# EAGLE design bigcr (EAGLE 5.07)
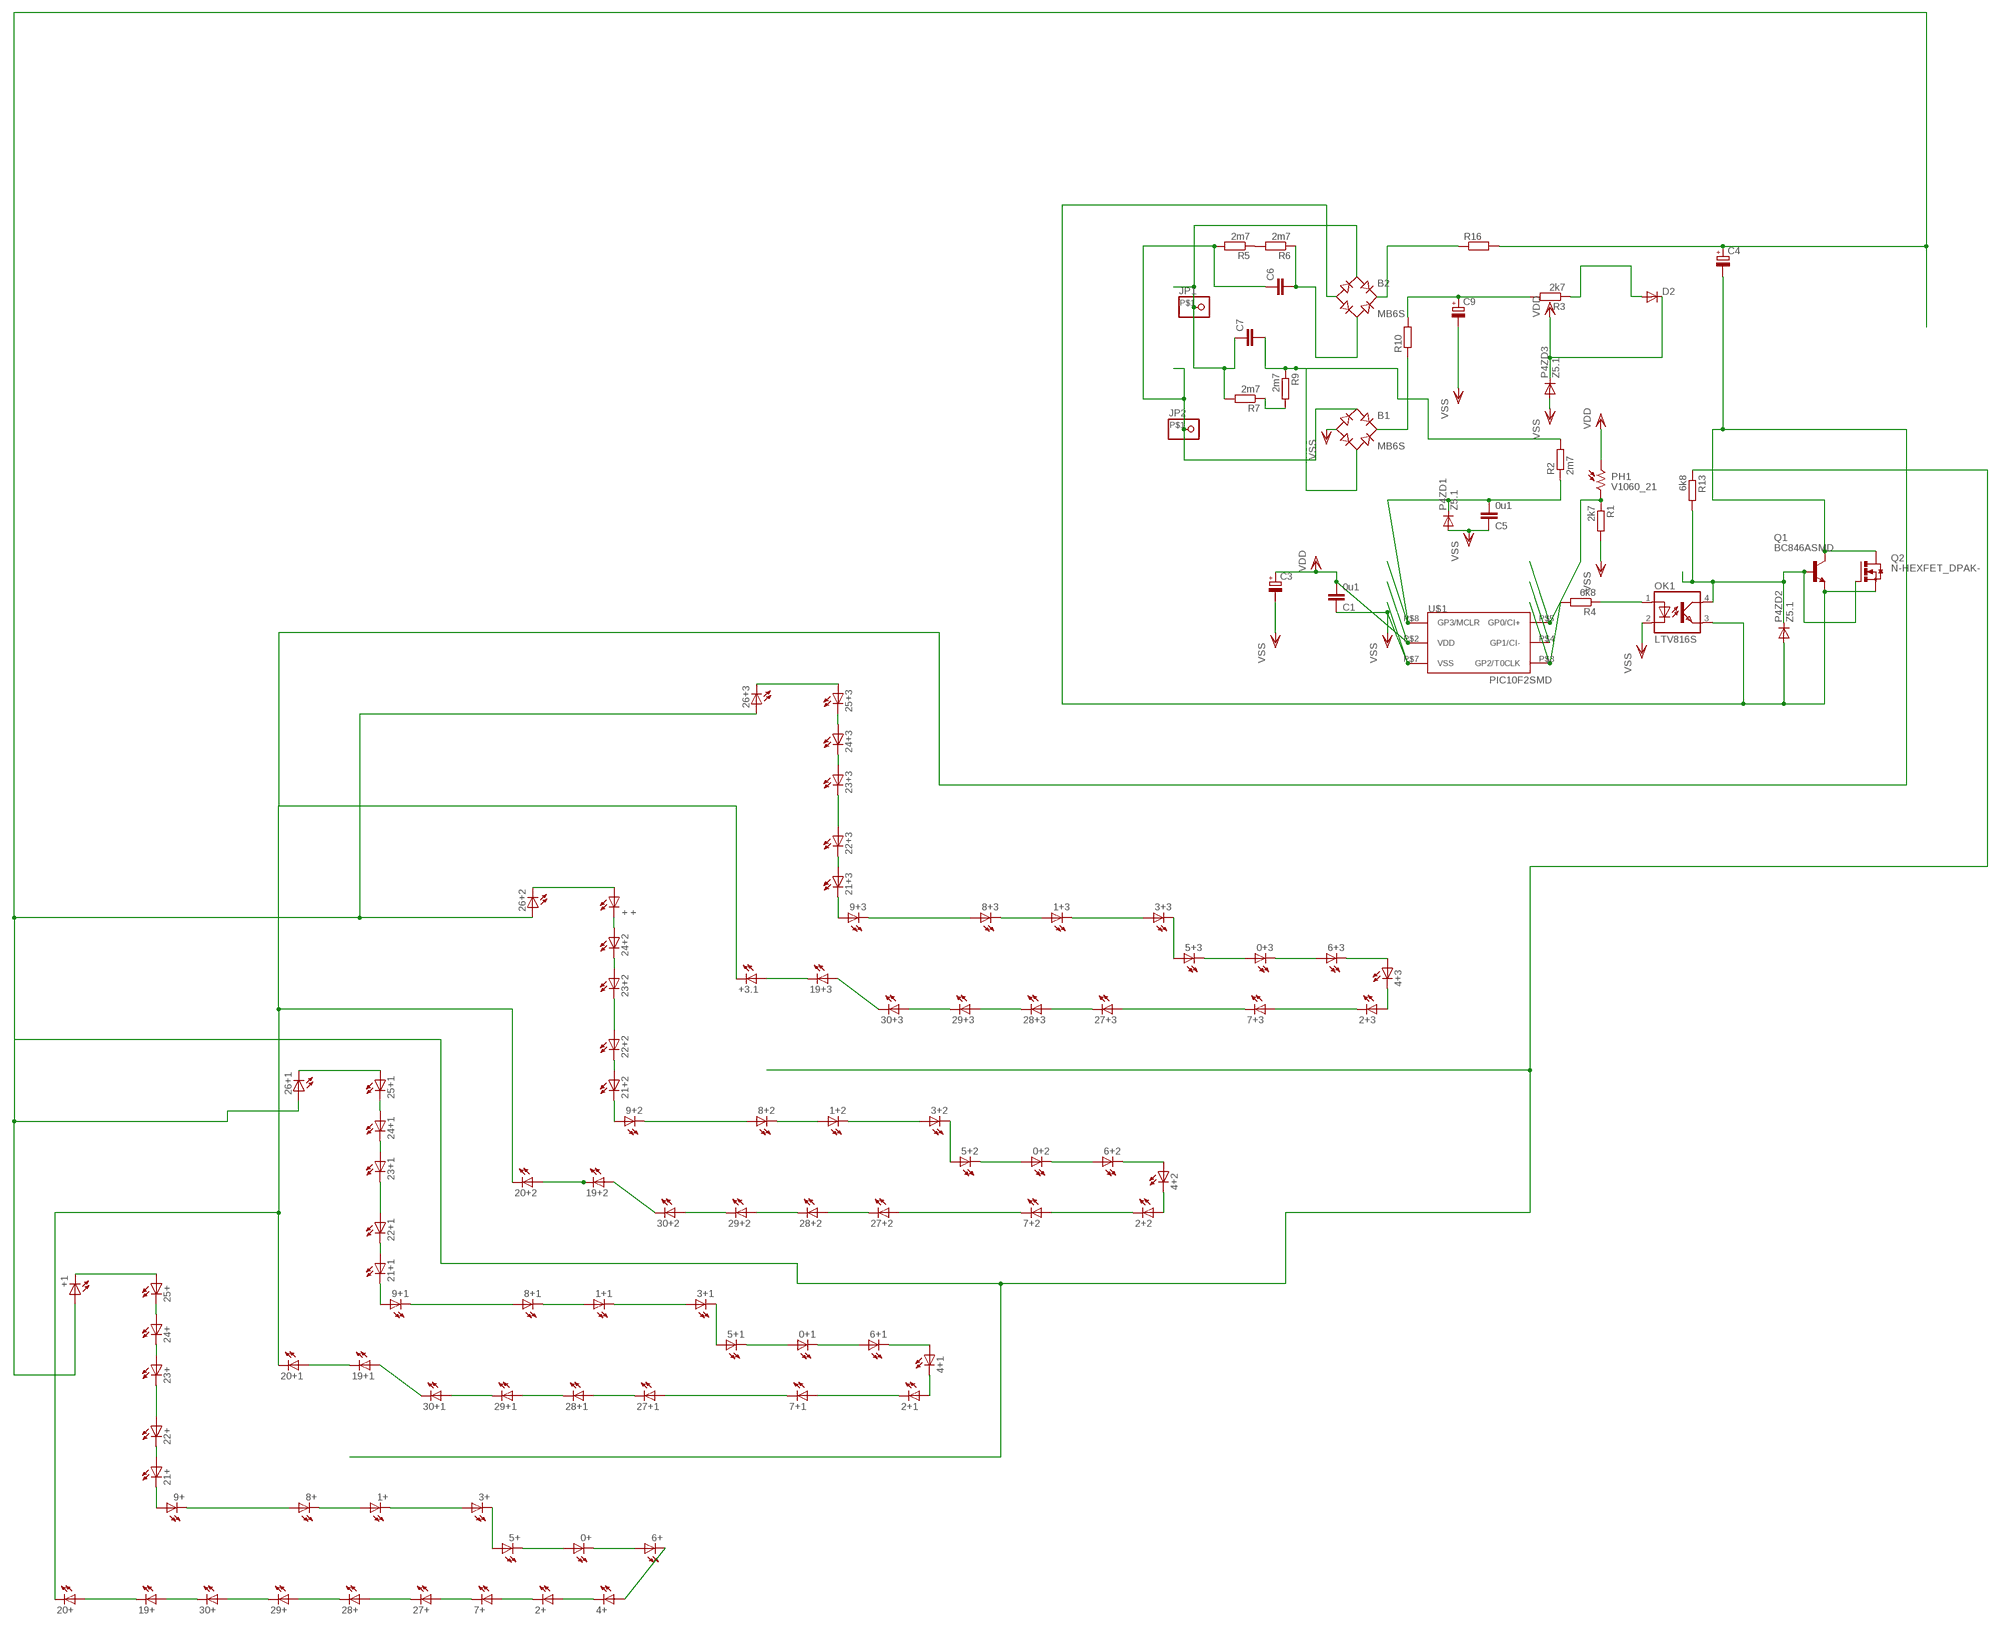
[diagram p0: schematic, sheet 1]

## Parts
0+  LED1210  [1210]
0+1  LED1210  [1210]
0+2  LED1210  [1210]
0+3  LED1210  [1210]
1+  LED1210  [1210]
1+1  LED1210  [1210]
1+2  LED1210  [1210]
1+3  LED1210  [1210]
2+  LED1210  [1210]
2+1  LED1210  [1210]
2+2  LED1210  [1210]
2+3  LED1210  [1210]
3+  LED1210  [1210]
3+1  LED1210  [1210]
3+2  LED1210  [1210]
3+3  LED1210  [1210]
4+  LED1210  [1210]
4+1  LED1210  [1210]
4+2  LED1210  [1210]
4+3  LED1210  [1210]
5+  LED1210  [1210]
5+1  LED1210  [1210]
5+2  LED1210  [1210]
5+3  LED1210  [1210]
6+  LED1210  [1210]
6+1  LED1210  [1210]
6+2  LED1210  [1210]
6+3  LED1210  [1210]
7+  LED1210  [1210]
7+1  LED1210  [1210]
7+2  LED1210  [1210]
7+3  LED1210  [1210]
8+  LED1210  [1210]
8+1  LED1210  [1210]
8+2  LED1210  [1210]
8+3  LED1210  [1210]
9+  LED1210  [1210]
9+1  LED1210  [1210]
9+2  LED1210  [1210]
9+3  LED1210  [1210]
19+  LED1210  [1210]
19+1  LED1210  [1210]
19+2  LED1210  [1210]
19+3  LED1210  [1210]
20+  LED1210  [1210]
20+1  LED1210  [1210]
20+2  LED1210  [1210]
21+  LED1210  [1210]
21+1  LED1210  [1210]
21+2  LED1210  [1210]
21+3  LED1210  [1210]
22+  LED1210  [1210]
22+1  LED1210  [1210]
22+2  LED1210  [1210]
22+3  LED1210  [1210]
23+  LED1210  [1210]
23+1  LED1210  [1210]
23+2  LED1210  [1210]
23+3  LED1210  [1210]
24+  LED1210  [1210]
24+1  LED1210  [1210]
24+2  LED1210  [1210]
24+3  LED1210  [1210]
25+  LED1210  [1210]
25+1  LED1210  [1210]
25+3  LED1210  [1210]
26+1  LED1210  [1210]
26+2  LED1210  [1210]
26+3  LED1210  [1210]
27+  LED1210  [1210]
27+1  LED1210  [1210]
27+2  LED1210  [1210]
27+3  LED1210  [1210]
28+  LED1210  [1210]
28+1  LED1210  [1210]
28+2  LED1210  [1210]
28+3  LED1210  [1210]
29+  LED1210  [1210]
29+1  LED1210  [1210]
29+2  LED1210  [1210]
29+3  LED1210  [1210]
30+  LED1210  [1210]
30+1  LED1210  [1210]
30+2  LED1210  [1210]
30+3  LED1210  [1210]
+  +  LED1210  [1210]
+1  LED1210  [1210]
+3.1  LED1210  [1210]
B1  MB6S  [SOIC-4]
B2  MB6S  [SOIC-4]
C1  0u1  C-EUC1206  [C1206]
C3  CPOL-EUD  [PANASONIC_D]
C4  CPOL-EUSANYO_SMD_F12  [SANYO-OSCON_SMD_F12]
C5  0u1  C-EUC1206  [C1206]
C6  C-EUSMD200  [SMD200]
C7  C-EUSMD100  [SMD100]
C9  CPOL-EUD  [PANASONIC_D]
D2  DIODE-MINIMELF  [MINIMELF]
JP1  PINHD-1X1SMD  [SMD1X1]
JP2  PINHD-1X1SMD  [SMD1X1]
OK1  LTV816S  [SMD4]
P4ZD1  Z5.1  DIODE-MINIMELF  [MINIMELF]
P4ZD2  Z5.1  DIODE-MINIMELF  [MINIMELF]
P4ZD3  Z5.1  DIODE-MINIMELF  [MINIMELF]
PH1  V1060_21  [TO-5_V10]
Q1  BC846ASMD  [SOT23]
Q2  N-HEXFET_DPAK-  [TO252]
R1  2k7  R-EU_R1206  [R1206]
R2  2m7  R-EU_R1206  [R1206]
R3  2k7  R-EU_R1206  [R1206]
R4  6k8  R-EU_R1206  [R1206]
R5  2m7  R-EU_R1210  [R1210]
R6  2m7  R-EU_R1210  [R1210]
R7  2m7  R-EU_R1210  [R1210]
R9  2m7  R-EU_R1210  [R1210]
R10  R-EU_SMD15  [SMDCARB15]
R13  6k8  R-EU_R1206  [R1206]
R16  R-EU_SMD15  [SMDCARB15]
U$1  PIC10F2SMD  [DIL8SMD]

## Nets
AC1: B1.~1(AC1) C6.P$1 JP2.P$1 R5.2
AC2: B2.~1(AC1) C7.P$1 JP1.P$1 R7.2
CBIG: B2.~2(AC2) C6.P$2 R6.1
CSMALL: B1.~2(AC2) C7.P$2 R2.2 R9.1
D+: 26+1.P$1(A) 26+2.P$1(A) 26+3.P$1(A) +1.P$1(A) C4.+ R13.1 R16.P$2
DR+: C9.+ R3.2 R10.P$2
MINUS: 20+1.P$2(C) 20+2.P$2(C) 20+.P$2(C) +3.1.P$2(C) C4.- Q1.3(C) Q2.3(D)
N$2: 19+.P$2(C) 20+.P$1(A)
N$4: 19+.P$1(A) 30+.P$2(C)
N$5: 19+1.P$1(A) 30+1.P$2(C)
N$6: 8+.P$1(A) 9+.P$2(C)
N$7: 29+.P$2(C) 30+.P$1(A)
N$8: 28+.P$2(C) 29+.P$1(A)
N$9: 27+.P$2(C) 28+.P$1(A)
N$10: 29+1.P$2(C) 30+1.P$1(A)
N$11: 28+1.P$2(C) 29+1.P$1(A)
N$12: 2+.P$2(C) 7+.P$1(A)
N$13: 7+.P$2(C) 27+.P$1(A)
N$14: 2+.P$1(A) 4+.P$2(C)
N$15: 4+.P$1(A) 6+.P$2(C)
N$16: 0+.P$2(C) 6+.P$1(A)
N$17: 0+.P$1(A) 5+.P$2(C)
N$18: 3+.P$2(C) 5+.P$1(A)
N$19: 1+.P$2(C) 3+.P$1(A)
N$20: 1+.P$1(A) 8+.P$2(C)
N$21: 27+1.P$2(C) 28+1.P$1(A)
N$22: 2+1.P$1(A) 4+1.P$2(C)
N$23: 9+.P$1(A) 21+.P$2(C)
N$24: 21+.P$1(A) 22+.P$2(C)
N$25: 22+.P$1(A) 23+.P$2(C)
N$26: 24+.P$1(A) 25+.P$2(C)
N$27: 25+.P$1(A) +1.P$2(C)
N$28: 23+.P$1(A) 24+.P$2(C)
N$29: 4+1.P$1(A) 6+1.P$2(C)
N$30: 0+1.P$2(C) 6+1.P$1(A)
N$31: 0+1.P$1(A) 5+1.P$2(C)
N$32: 3+1.P$2(C) 5+1.P$1(A)
N$33: 1+1.P$2(C) 3+1.P$1(A)
N$34: 1+1.P$1(A) 8+1.P$2(C)
N$35: 9+1.P$1(A) 21+1.P$2(C)
N$36: 21+1.P$1(A) 22+1.P$2(C)
N$37: 22+1.P$1(A) 23+1.P$2(C)
N$38: 25+1.P$1(A) 26+1.P$2(C)
N$39: 24+1.P$1(A) 25+1.P$2(C)
N$40: 23+1.P$1(A) 24+1.P$2(C)
N$41: 2+1.P$2(C) 7+1.P$1(A)
N$42: 7+1.P$2(C) 27+1.P$1(A)
N$43: 8+1.P$1(A) 9+1.P$2(C)
N$44: 19+1.P$2(C) 20+1.P$1(A)
N$45: 19+2.P$1(A) 30+2.P$2(C)
N$46: 29+2.P$2(C) 30+2.P$1(A)
N$47: 28+2.P$2(C) 29+2.P$1(A)
N$48: 27+2.P$2(C) 28+2.P$1(A)
N$49: 2+2.P$1(A) 4+2.P$2(C)
N$50: 4+2.P$1(A) 6+2.P$2(C)
N$51: 0+2.P$2(C) 6+2.P$1(A)
N$52: 0+2.P$1(A) 5+2.P$2(C)
N$53: 3+2.P$2(C) 5+2.P$1(A)
N$54: 1+2.P$2(C) 3+2.P$1(A)
N$55: 1+2.P$1(A) 8+2.P$2(C)
N$56: 9+2.P$1(A) 21+2.P$2(C)
N$57: 21+2.P$1(A) 22+2.P$2(C)
N$58: 22+2.P$1(A) 23+2.P$2(C)
N$59: 26+2.P$2(C) +.P$1(A)
N$60: 24+2.P$1(A) +.P$2(C)
N$61: 23+2.P$1(A) 24+2.P$2(C)
N$62: 2+2.P$2(C) 7+2.P$1(A)
N$63: 7+2.P$2(C) 27+2.P$1(A)
N$64: 8+2.P$1(A) 9+2.P$2(C)
N$65: 19+2.P$2(C) 20+2.P$1(A)
N$66: 19+3.P$1(A) 30+3.P$2(C)
N$67: 29+3.P$2(C) 30+3.P$1(A)
N$68: 28+3.P$2(C) 29+3.P$1(A)
N$69: 27+3.P$2(C) 28+3.P$1(A)
N$70: 2+3.P$1(A) 4+3.P$2(C)
N$71: 4+3.P$1(A) 6+3.P$2(C)
N$72: 0+3.P$2(C) 6+3.P$1(A)
N$73: 0+3.P$1(A) 5+3.P$2(C)
N$74: 3+3.P$2(C) 5+3.P$1(A)
N$75: 1+3.P$2(C) 3+3.P$1(A)
N$76: 1+3.P$1(A) 8+3.P$2(C)
N$77: 9+3.P$1(A) 21+3.P$2(C)
N$78: 21+3.P$1(A) 22+3.P$2(C)
N$79: 22+3.P$1(A) 23+3.P$2(C)
N$80: 25+3.P$1(A) 26+3.P$2(C)
N$81: 24+3.P$1(A) 25+3.P$2(C)
N$82: 23+3.P$1(A) 24+3.P$2(C)
N$83: 2+3.P$2(C) 7+3.P$1(A)
N$84: 7+3.P$2(C) 27+3.P$1(A)
N$85: 8+3.P$1(A) 9+3.P$2(C)
N$86: C5.2 P4ZD1.C R2.1 U$1.P$8(GP3/MCLR)
N$87: OK1.1(A) R4.1
N$88: PH1.2 R1.1 U$1.P$5(GP0/CI+)
N$89: R5.1 R6.2
N$90: R7.1 R9.2
N$91: B2.+ R16.P$1
N$92: D2.A R3.1
N$93: B2.- OK1.3(EMIT) P4ZD2.A Q1.2(E) Q2.2(S)
N$94: OK1.4(COL) P4ZD2.C Q1.1(B) Q2.1(G) R13.2
N$95: R4.2 U$1.P$3(GP2/T0CLK)
N$97: 19+3.P$2(C) +3.1.P$1(A)
N$102: U$1.P$4(GP1/CI-)
RECDR+: B1.+ R10.P$1
VDD: C1.2 C3.+ D2.C P4ZD3.C PH1.1 U$1.P$2(VDD)
VSS: B1.- C1.1 C3.- C5.1 C9.- OK1.2(C) P4ZD1.A P4ZD3.A R1.2 U$1.P$7(VSS)

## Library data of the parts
0+ 0+1-0+3 1+ 1+1-1+3 2+ 2+1-2+3 3+ 3+1-3+3 4+ 4+1-4+3 5+ 5+1-5+3 6+ 6+1-6+3 7+ 7+1-7+3 8+ 8+1-8+3 9+ 9+1-9+3 19+ 19+1-19+3 20+ 20+1 20+2 21+ 21+1-21+3 22+ 22+1-22+3 23+ 23+1-23+3 24+ 24+1-24+3 25+ 25+1 25+3 26+1-26+3 27+ 27+1-27+3 28+ 28+1-28+3 29+ 29+1-29+3 30+ 30+1-30+3 + +1 +3.1 = led(2):LED: LED
B1 B2 = rectifier:MB*S: Bridge Rectifier Source: http://www.fairchildsemi.com/ds/MB/MB6S.pdf
C1 C5-C7 = rcl:C-EU: CAPACITOR, European symbol
C3 C4 C9 = rcl-2:CPOL-EU: POLARIZED CAPACITOR, European symbol
D2 P4ZD1-P4ZD3 = diode:DIODE-: DIODE
JP1 JP2 = pinhead:PINHD-1X1: PIN HEADER
OK1 = optocoupler:LTV816: OPTO COUPLER Source: LITEON, LTV816.pdf
PH1 = photo-elements:?1060*: Sensor Street Light control
Q1 = transistor-npn:BC846*: NPN Transistor
Q2 = transistor-power:N-HEXFET_?-*: HEXFET® Power MOSFET
R1-R7 R9 R13 = rcl-2:R-EU_: RESISTOR, European symbol
R10 R16 = rcl:R-EU_: RESISTOR, European symbol
U$1 = microchip-5:PIC10F2*: uPC nW 0,25/0,5k Program Flash memory Comparator

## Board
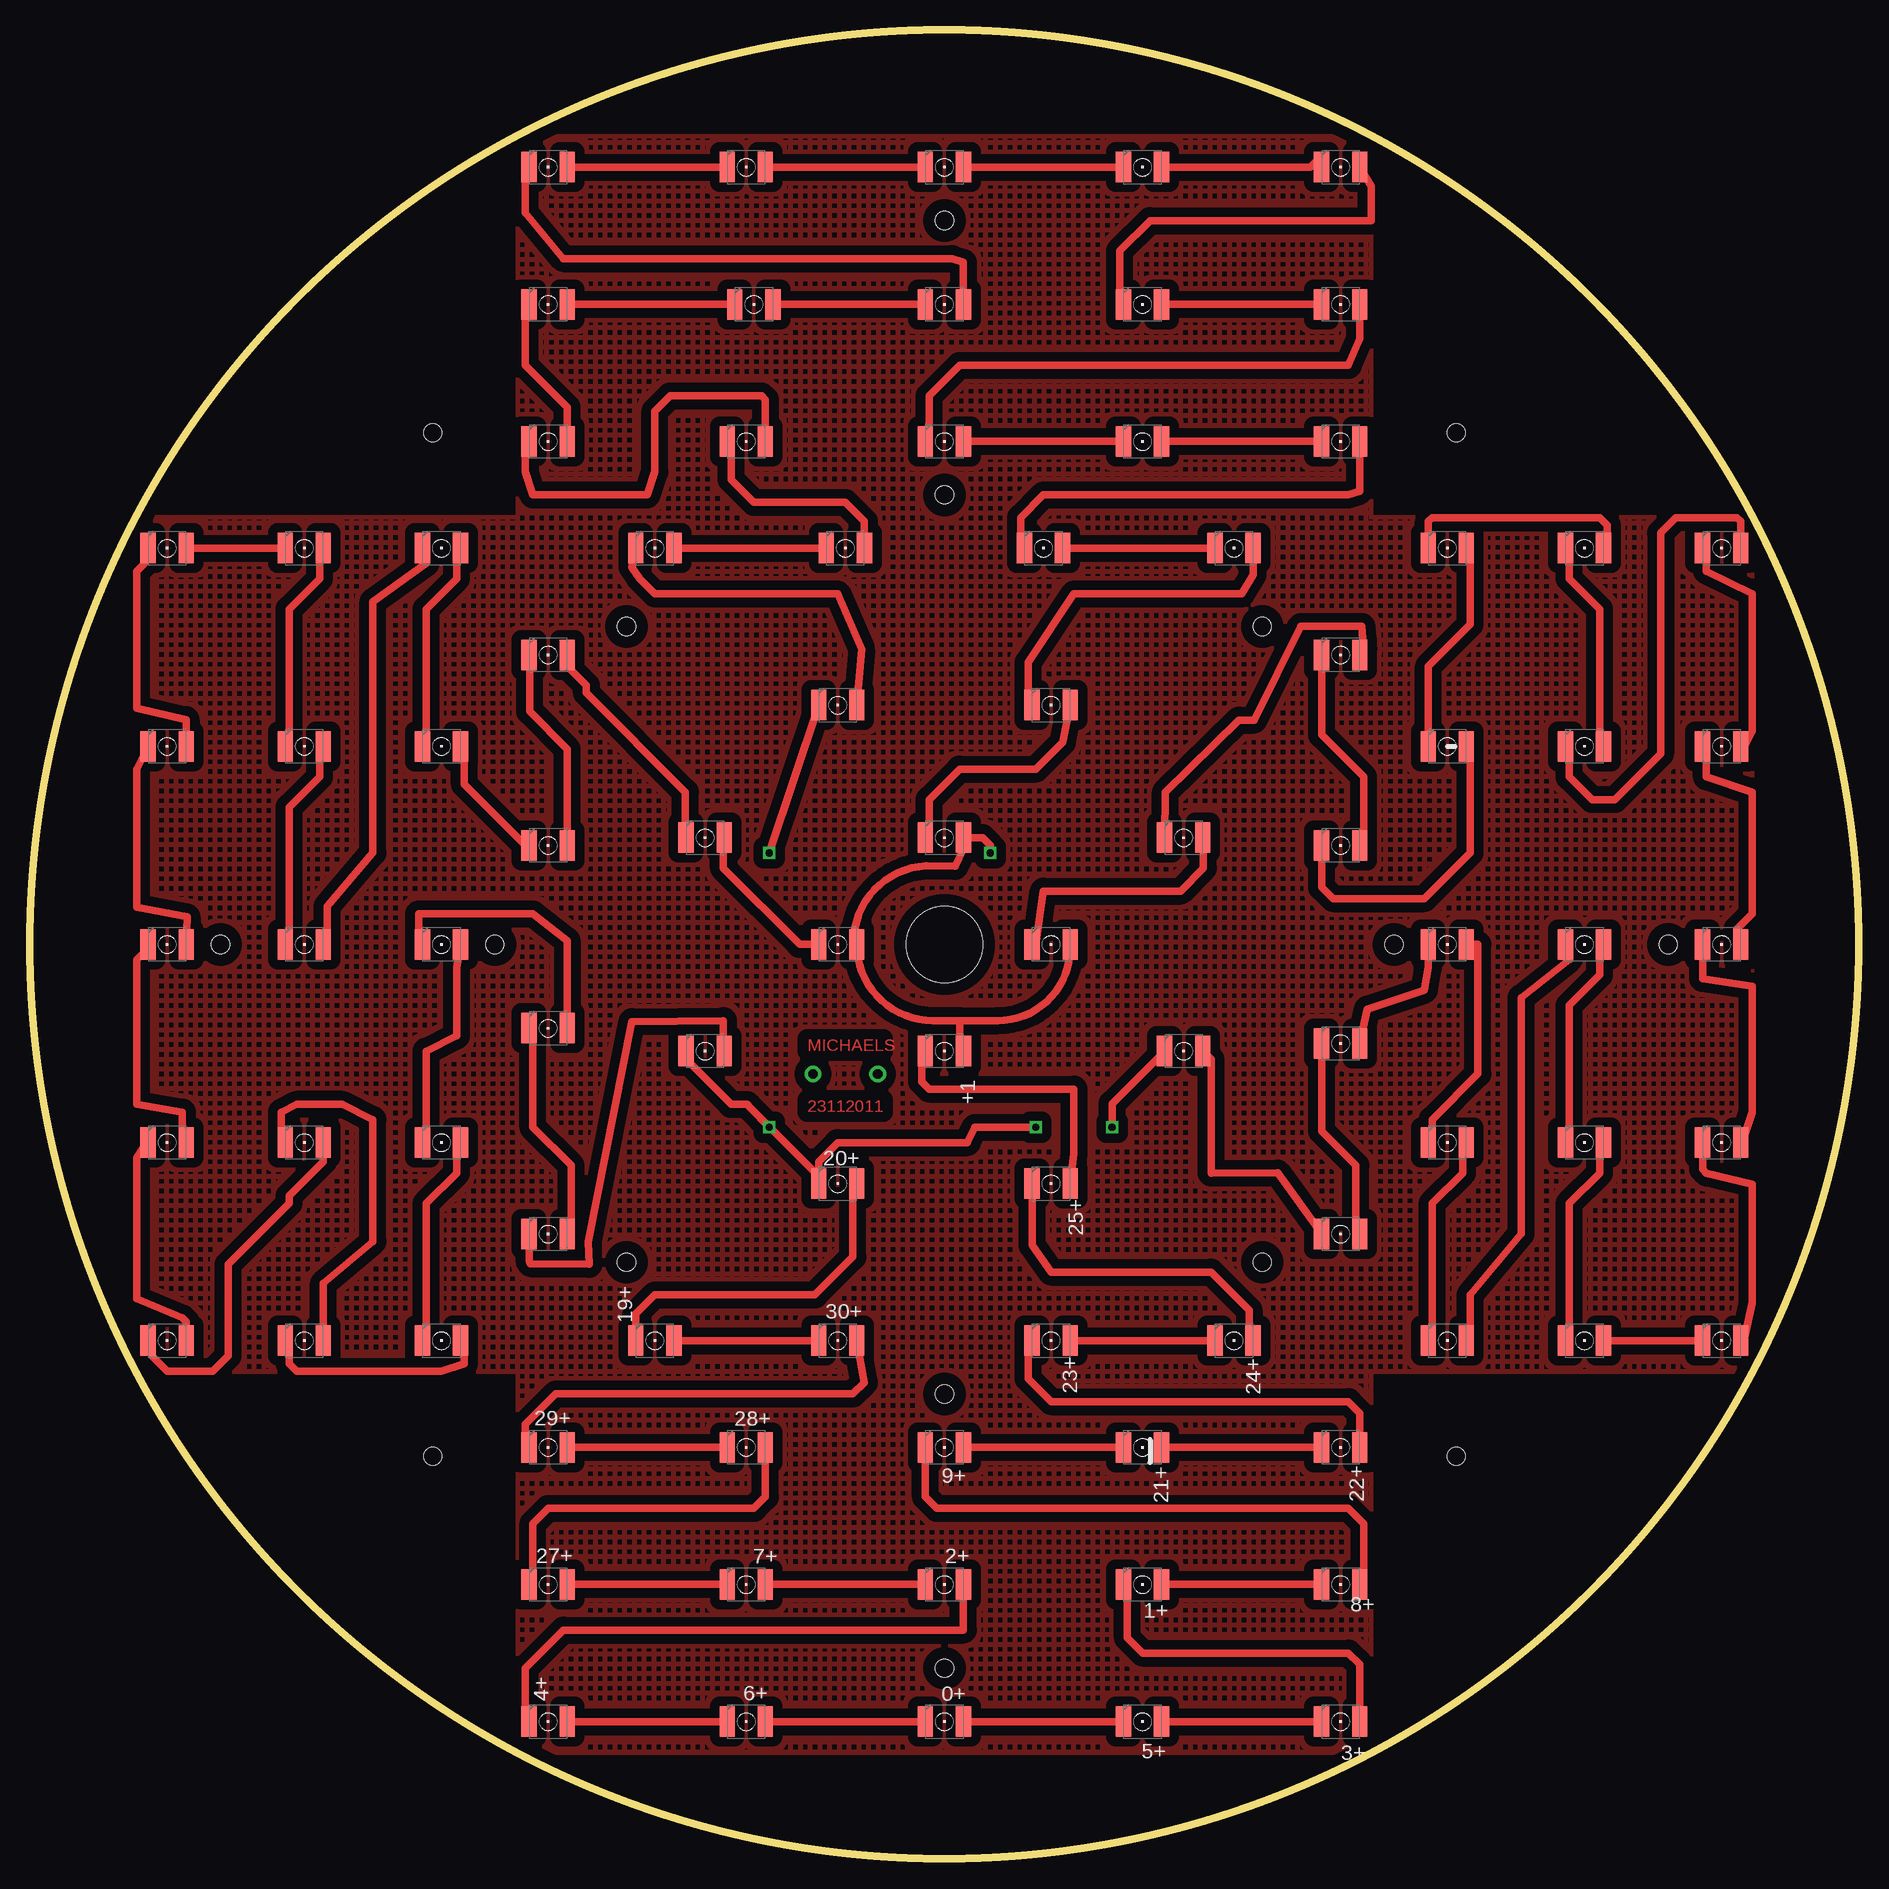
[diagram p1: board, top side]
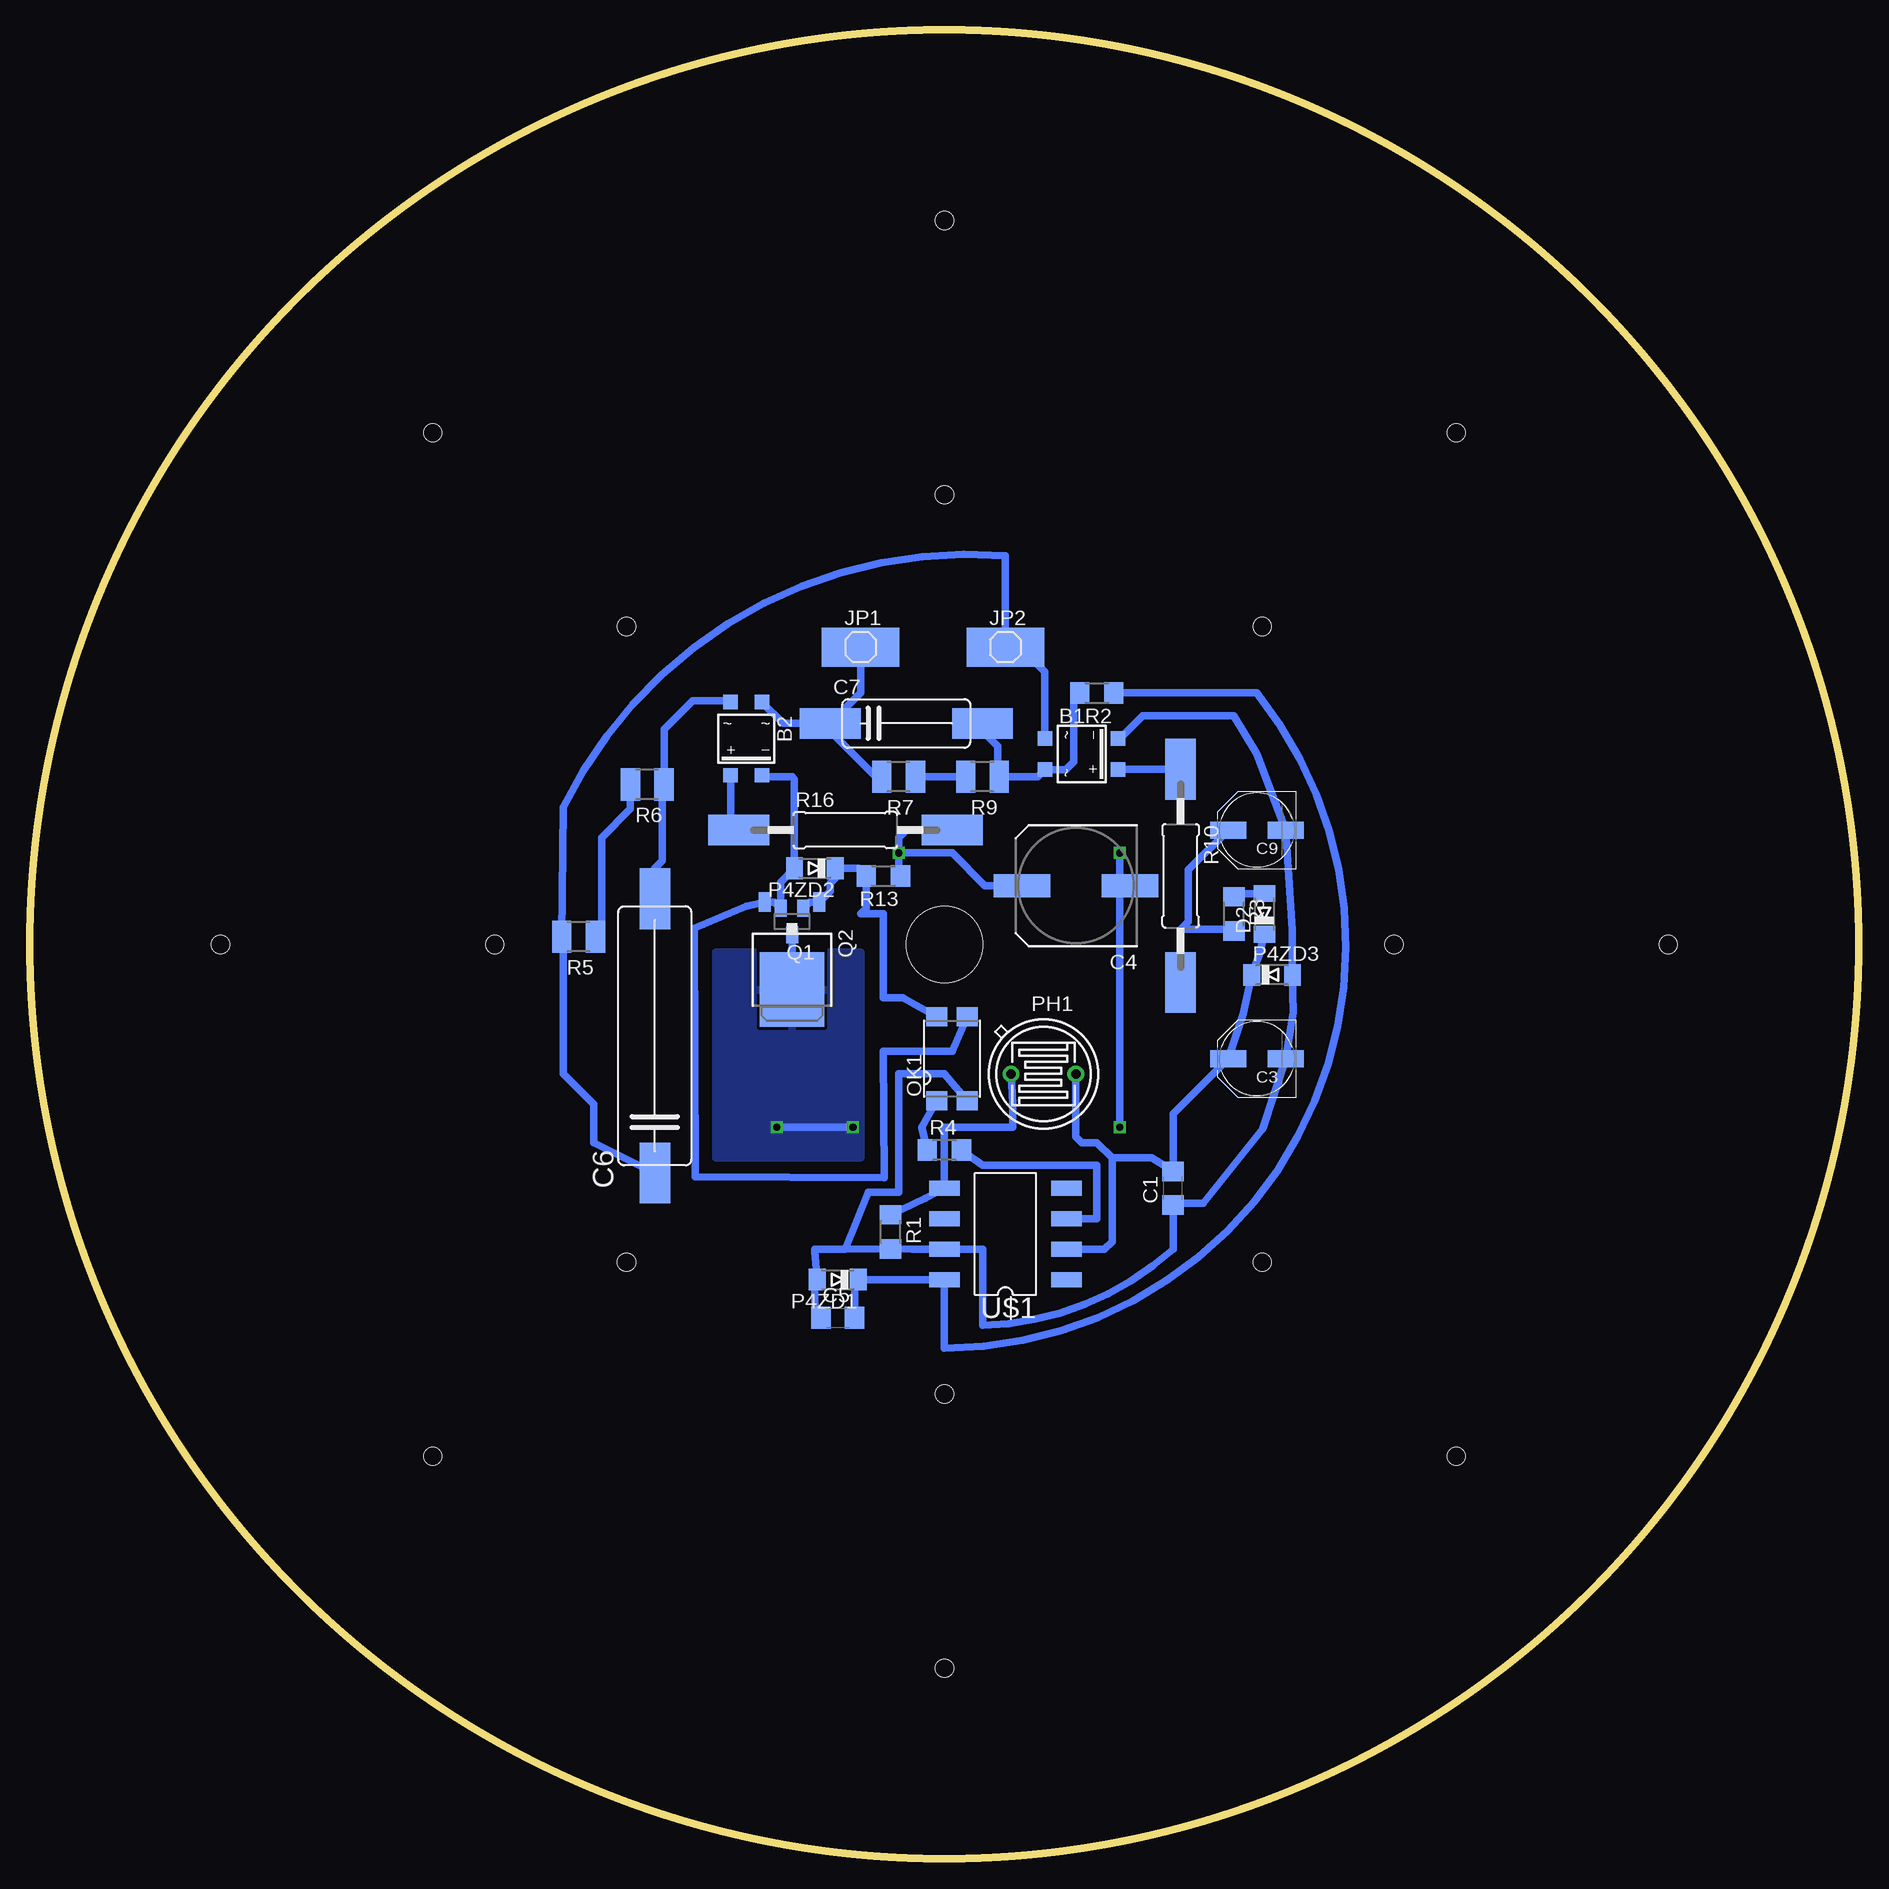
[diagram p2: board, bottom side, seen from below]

Size 152.4 x 152.4 mm. Coordinates in mm from the lower left corner, seen from the top.
Outline: circle at 76.2,76.2 radius 76.2
Copper layers (1*16): Top 0.035mm / dielectric 1.5mm / Bottom 0.035mm
Design rules "default": minimum track width 10mil, minimum drill 24mil, track to track 8mil, track to pad 8mil, pad to pad 8mil, via to via 8mil, smd to smd 8mil, copper to edge 40mil, drill to drill 8mil, minimum pad ring 10mil, minimum via ring 8mil, stop-mask expansion 4mil, vias tented up to drill 0mil, thermal gap 10mil
Holes 6.35 mm at 76.2,76.2
Holes 1.5 mm at 136.53,76.2 118.85,33.55 118.85,118.85 33.55,118.85 76.2,136.53 15.88,76.2 33.55,33.55 76.2,15.88 76.2,38.73 76.2,113.67 113.67,76.2 38.73,76.2 49.71,102.69 102.69,102.69 102.69,49.71 49.71,49.71

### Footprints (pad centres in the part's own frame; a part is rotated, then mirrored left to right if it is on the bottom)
1210 = smd 1.27 x 2.54: P$1 1.587,0; P$2 -1.587,0
SOIC-4 = smd 1.2 x 1.2: + 1.3,3.05; - -1.3,3.05; ~1 -1.3,-3.05; ~2 1.3,-3.05
C1206 = smd 1.6 x 1.8: 1 -1.4,0; 2 1.4,0
PANASONIC_D = smd 3 x 1.4: + 2.4,0; - -2.4,0
SANYO-OSCON_SMD_F12 = smd 4.7 x 1.9: + 4.5,0; - -4.5,0
SMD200 = smd 5.08 x 2.54: P$1 -10.16,0; P$2 12.7,0
SMD100 = smd 5.08 x 2.54: P$1 -6.35,0; P$2 6.35,0
MINIMELF = smd 1.4 x 1.8: A 1.7,0; C -1.7,0
SMD1X1 = smd 6.452 x 3.251: P$1 0,0
SMD4 = smd 1.78 x 1.55: 1 -1.27,-3.5; 2 1.27,-3.5; 3 1.27,3.5; 4 -1.27,3.5
TO-5_V10 = drill 0.8 pad 1.4 round: 1 -2.7,0; 2 2.7,0
SOT23 = smd 1 x 1.4: 1 -0.95,-1.1; 2 0.95,-1.1; 3 0,1.1
TO252 = smd 1 x 1.6: 1 -2.28,-3.53; 2 2.28,-3.53 | smd 5.4 x 6.2: 3 0,3.77
R1206 = smd 1.6 x 1.803: 1 -1.422,0; 2 1.422,0
R1210 = smd 1.6 x 2.7: 1 -1.4,0; 2 1.4,0
SMDCARB15 = smd 5.08 x 2.54: P$1 -8.89,0; P$2 8.89,0
DIL8SMD = smd 1.27 x 2.54: P$1 -3.81,-5.08; P$2 -1.27,-5.08; P$3 1.27,-5.08; P$4 3.81,-5.08; P$5 3.81,5.08; P$6 1.27,5.08; P$7 -1.27,5.08; P$8 -3.81,5.08

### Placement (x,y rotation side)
0+  76.2,11.43 0 top
0+1  140.97,59.69 0 top
0+2  76.2,140.97 0 top
0+3  11.43,76.2 0 top
1+  92.71,22.86 0 top
1+1  140.97,109.22 0 top
1+2  92.71,129.54 0 top
1+3  22.86,109.22 0 top
2+  76.2,22.86 0 top
2+1  129.54,59.69 0 top
2+2  76.2,129.54 0 top
2+3  22.86,59.69 0 top
3+  109.22,11.43 0 top
3+1  140.97,92.71 0 top
3+2  109.22,140.97 0 top
3+3  11.43,109.22 0 top
4+  43.18,11.43 0 top
4+1  129.54,43.18 0 top
4+2  43.18,140.97 0 top
4+3  11.43,43.18 0 top
5+  92.71,11.43 0 top
5+1  140.97,76.2 0 top
5+2  92.71,140.97 0 top
5+3  11.43,92.71 0 top
6+  59.69,11.43 0 top
6+1  140.97,43.18 0 top
6+2  59.69,140.97 0 top
6+3  11.43,59.69 0 top
7+  59.69,22.86 0 top
7+1  129.54,76.2 0 top
7+2  60.33,129.54 0 top
7+3  22.86,43.18 0 top
8+  109.22,22.86 0 top
8+1  129.54,92.71 0 top
8+2  109.22,129.54 0 top
8+3  22.86,92.71 0 top
9+  76.2,34.29 0 top
9+1  129.54,109.22 0 top
9+2  76.2,118.11 0 top
9+3  22.86,76.2 0 top
19+  52.07,43.18 0 top
19+1  109.22,52.07 0 top
19+2  52.07,109.22 0 top
19+3  43.18,52.07 0 top
20+  67.31,56.26 0 top
20+1  96.14,67.31 0 top
20+2  67.31,96.14 0 top
21+  92.71,34.29 0 top
21+1  118.11,109.22 0 top
21+2  92.71,118.11 0 top
21+3  34.29,109.22 0 top
22+  109.22,34.29 0 top
22+1  118.11,92.71 0 top
22+2  109.22,118.11 0 top
22+3  34.29,92.71 0 top
23+  85.09,43.18 0 top
23+1  109.22,84.45 0 top
23+2  84.45,109.22 0 top
23+3  43.18,84.45 0 top
24+  100.33,43.18 0 top
24+1  109.22,100.33 0 top
24+2  100.33,109.22 0 top
24+3  43.18,100.33 0 top
25+  85.09,56.26 0 top
25+1  96.14,85.09 0 top
25+3  56.26,85.09 0 top
26+1  85.09,76.2 0 top
26+2  76.2,85.09 0 top
26+3  67.31,76.2 0 top
27+  43.18,22.86 0 top
27+1  118.11,43.18 0 top
27+2  43.18,129.54 0 top
27+3  34.29,43.18 0 top
28+  59.69,34.29 0 top
28+1  118.11,59.69 0 top
28+2  43.18,118.11 0 top
28+3  34.29,59.69 0 top
29+  43.18,34.29 0 top
29+1  118.11,76.2 0 top
29+2  59.69,118.11 0 top
29+3  34.29,76.2 0 top
30+  67.31,43.18 0 top
30+1  109.22,67.94 0 top
30+2  67.94,109.22 0 top
30+3  43.18,69.22 0 top
+  85.09,96.14 0 top
+1  76.2,67.31 0 top
+3.1  56.26,67.31 0 top
B1  64.77,92.08 270 bottom
B2  92.71,93.34 180 bottom
C1  57.15,55.88 90 bottom
C3  50.16,66.67 180 bottom
C4  65.22,81.09 180 bottom
C5  85.09,45.09 0 bottom
C6  100.33,67.31 90 bottom
C7  79.38,94.61 0 bottom
C9  50.16,85.72 180 bottom
D2  49.53,78.74 90 bottom
JP1  83.19,100.97 0 bottom
JP2  71.12,100.97 0 bottom
OK1  75.56,66.67 0 bottom
P4ZD1  85.09,48.26 180 bottom
P4ZD2  87,82.55 180 bottom
P4ZD3  48.9,73.66 0 bottom
PH1  67.94,65.41 180 bottom
Q1  88.9,78.11 180 bottom
Q2  88.9,76.2 180 bottom
R1  80.69,52.24 270 bottom
R2  63.5,97.16 180 bottom
R3  52.07,78.74 270 bottom
R4  76.2,59.05 0 bottom
R5  106.68,76.83 180 bottom
R6  100.97,89.53 180 bottom
R7  80.01,90.17 180 bottom
R9  73.03,90.17 180 bottom
R10  56.52,81.92 270 bottom
R13  81.28,81.92 180 bottom
R16  84.45,85.72 0 bottom
U$1  71.12,52.07 90 bottom

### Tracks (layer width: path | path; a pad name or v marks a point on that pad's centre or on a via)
AC1
  Bottom 0.61: B1.~1 67.82,98.94 69.85,100.97 JP2.P$1 71.12,108.58 arc-69 107.95,87.63 R5.2 107.95,76.7 107.95,65.41 105.41,62.87 105.41,59.69 C6.P$1
AC2
  Bottom 0.61: R7.2 81.92,90.17 86.36,94.61 C7.P$1 | JP1.P$1 83.19,97.16 C7.P$1 | C7.P$1 89.63,94.61 B2.~1
CBIG
  Bottom 0.61: B2.~2 94.14,96.52 97.16,96.52 99.56,94.11 R6.1 99.69,89.41 99.69,83.19 100.33,82.55 C6.P$2
CSMALL
  Bottom 0.61: R2.2 65.41,96.67 65.41,91.44 66.07,90.78 B1.~2 68.42,90.17 R9.1 71.75,90.3 71.75,92.71 73.03,93.98 C7.P$2
D+  (via drill 0.6)
  Top 0.61: +1.P$1 77.47,67.63 77.47,69.85 | 77.47,69.85 75.25,69.85 arc-90 26+3.P$1 69.22,76.52 68.74,77.55 arc-77 74.68,82.75 77.09,82.71 77.79,84.14 26+2.P$1 79.38,85.09 80.01,84.45 v80.01,83.82 | 26+1.P$1 86.68,75.88 arc-90 80.64,69.85 77.47,69.85
  Bottom 0.61: R13.1 80.01,81.92 v80.01,83.82 | C4.+ 72.84,81.09 75.56,83.82 v80.01,83.82 | R16.P$2 79.38,85.72 80.01,85.09 v80.01,83.82
DR+
  Bottom 0.61: C9.+ 55.88,82.41 55.88,78.11 56.52,77.47 | R10.P$2 56.52,77.47 | R3.2 52.22,77.47 56.52,77.47
MINUS  (via drill 0.6)
  Top 0.61: +3.1.P$2 54.67,66.61 58.42,62.87 59.75,62.87 60.04,62.58 | v61.59,83.82 20+2.P$2 | 20+1.P$2 90.17,62.93 v90.17,60.96 | v83.82,60.96 78.74,60.96 78.11,59.69 67.31,59.69 65.72,58.1 20+.P$2 65.72,56.9 60.04,62.58 | 60.04,62.58 v61.59,60.96 | 60.04,62.58
  Bottom 0.61: Q2.3 Q1.3 | v83.82,60.96 v90.17,60.96 | v61.59,83.82 61.59,81.33 C4.- 61.59,80.7 v61.59,60.96
  pour Bottom: 83.82,75.56 95.25,75.56 95.25,74.3 95.25,58.42 83.19,58.42 83.19,75.56
N$2
  Top 0.61: 19+.P$2 50.48,45.4 52.07,46.99 65.41,46.99 68.58,50.16 68.58,55.94 20+.P$1
N$3
  pour Top (isolate 0.813, hatched): 8.89,40.64 40.64,40.64 40.64,8.89 111.76,8.89 111.76,40.64 143.51,40.64 143.51,111.76 111.76,111.76 111.76,143.51 40.64,143.51 40.64,111.76 8.89,111.76
N$4
  Top 0.61: 19+.P$1 30+.P$2
N$5
  Top 0.61: 30+1.P$2 107.63,60.64 110.49,57.78 110.49,52.39 19+1.P$1
N$6
  Top 0.61: 9+.P$2 74.61,30.16 75.56,29.21 109.86,29.21 111.12,27.94 111.12,23.18 8+.P$1
N$7
  Top 0.61: 30+.P$1 69.53,39.69 68.58,38.73 43.81,38.73 41.27,36.2 41.27,34.61 29+.P$2
N$8
  Top 0.61: 29+.P$1 28+.P$2
N$9
  Top 0.61: 28+.P$1 61.28,30.16 60.33,29.21 43.18,29.21 41.91,27.94 41.91,23.18 27+.P$2
N$10
  Top 0.61: 30+1.P$1 111.44,70.8 116.2,72.39 116.52,74.3 29+1.P$2
N$11
  Top 0.61: 28+1.P$2 116.84,59.69 116.84,61.59 120.65,65.41 120.65,76.2 29+1.P$1
N$12
  Top 0.61: 7+.P$1 2+.P$2
N$13
  Top 0.61: 27+.P$1 7+.P$2
N$14
  Top 0.61: 2+.P$1 77.79,19.05 44.45,19.05 41.27,15.88 41.27,11.75 4+.P$2
N$15
  Top 0.61: 4+.P$1 6+.P$2
N$16
  Top 0.61: 6+.P$1 0+.P$2
N$17
  Top 0.61: 0+.P$1 5+.P$2
N$18
  Top 0.61: 5+.P$1 3+.P$2
N$19
  Top 0.61: 3+.P$1 110.81,16.19 109.86,17.14 92.71,17.14 91.44,18.41 91.44,22.54 1+.P$2
N$20
  Top 0.61: 1+.P$1 8+.P$2
N$21
  Top 0.61: 27+1.P$2 116.84,43.18 116.84,54.61 119.38,57.15 119.38,59.69 28+1.P$1
N$22
  Top 0.61: 4+1.P$2 128.27,43.18 128.27,54.61 130.81,57.15 130.81,59.69 2+1.P$1
N$23
  Top 0.61: 9+.P$1 21+.P$2
N$24
  Top 0.61: 21+.P$1 22+.P$2
N$25
  Top 0.61: 22+.P$1 110.81,37.15 109.86,38.1 85.09,38.1 83.19,40.01 83.19,42.86 23+.P$2
N$26
  Top 0.61: 25+.P$2 83.5,51.12 85.09,48.9 98.42,48.9 101.6,45.72 101.6,43.5 24+.P$1
N$27
  Top 0.61: 25+.P$1 87,58.74 87,64.14 74.93,64.14 74.3,64.77 74.3,66.99 +1.P$2
N$28
  Top 0.61: 23+.P$1 24+.P$2
N$29
  Top 0.61: 4+1.P$1 6+1.P$2
N$30
  Top 0.61: 0+1.P$2 139.38,57.47 139.7,57.15 143.51,56.2 143.51,46.35 142.88,43.5 6+1.P$1
N$31
  Top 0.61: 5+1.P$2 139.38,73.34 143.51,72.7 143.51,62.23 142.88,60.33 142.88,60.01 0+1.P$1
N$32
  Top 0.61: 142.88,76.2 5+1.P$1 142.24,76.52 142.24,77.47 143.51,78.74 143.51,88.9 139.7,90.17 139.7,92.71 3+1.P$2
N$33
  Top 0.61: 3+1.P$1 142.88,92.71 143.51,93.98 143.51,105.41 139.7,107.31 139.7,109.22 1+1.P$2
N$34
  Top 0.61: 1+1.P$1 142.56,111.44 142.24,111.76 137.16,111.76 135.89,110.49 135.89,92.08 132.08,88.27 130.18,88.27 128.27,90.17 128.27,92.39 8+1.P$2
N$35
  Top 0.61: 21+1.P$2 116.52,111.44 116.84,111.76 130.81,111.76 131.44,111.12 131.44,109.54 9+1.P$1
N$36
  Top 0.61: 22+1.P$2 116.52,99.38 120.02,102.87 120.02,109.22 21+1.P$1
N$37
  Top 0.61: 23+1.P$2 107.63,80.96 108.58,80.01 116.2,80.01 120.02,83.82 120.02,92.39 22+1.P$1
N$38
  Top 0.61: 26+1.P$2 83.82,76.2 84.45,80.64 95.89,80.64 97.79,82.55 97.79,84.39 25+1.P$1
N$39
  Top 0.61: 25+1.P$2 94.61,88.9 100.74,94.89 102.01,94.89 105.92,102.7 111,102.7 111.12,100.65 24+1.P$1
N$40
  Top 0.61: 24+1.P$2 107.63,93.66 111.12,90.17 111.12,84.77 23+1.P$1
N$41
  Top 0.61: 2+1.P$2 128.27,59.69 128.27,71.12 130.81,73.66 130.81,76.2 7+1.P$1
N$42
  Top 0.61: 27+1.P$1 120.02,43.18 120.02,46.99 124.27,52.07 124.27,71.75 128.27,74.93 128.27,76.2 7+1.P$2
N$43
  Top 0.61: 8+1.P$1 130.81,92.71 130.81,104.14 128.27,106.68 128.27,109.22 9+1.P$2
N$44
  Top 0.61: 19+1.P$2 103.97,57.17 98.42,57.15 98.42,66.61 20+1.P$1
N$45
  Top 0.61: 19+2.P$1 30+2.P$2
N$46
  Top 0.61: 30+2.P$1 69.53,111.44 67.94,113.03 60.33,113.03 58.42,114.94 58.42,117.79 29+2.P$2
N$47
  Top 0.61: 29+2.P$1 61.28,121.6 60.96,121.92 53.34,121.92 52.07,120.65 52.07,115.57 51.44,113.67 41.91,113.67 41.27,115.57 41.27,117.79 28+2.P$2
N$48
  Top 0.61: 28+2.P$1 44.77,120.97 41.27,124.46 41.27,129.22 27+2.P$2
N$49
  Top 0.61: 2+2.P$1 77.79,133.03 76.83,133.35 44.45,133.35 41.27,137.16 41.27,140.65 4+2.P$2
N$50
  Top 0.61: 4+2.P$1 6+2.P$2
N$51
  Top 0.61: 6+2.P$1 0+2.P$2
N$52
  Top 0.61: 0+2.P$1 5+2.P$2
N$53
  Top 0.61: 5+2.P$1 106.68,140.97 107.31,141.6 3+2.P$2
N$54
  Top 0.61: 3+2.P$1 111.76,139.38 111.76,136.53 93.34,136.53 90.81,133.99 90.81,129.86 1+2.P$2
N$55
  Top 0.61: 1+2.P$1 8+2.P$2
N$56
  Top 0.61: 9+2.P$1 21+2.P$2
N$57
  Top 0.61: 21+2.P$1 22+2.P$2
N$58
  Top 0.61: 22+2.P$1 110.81,113.98 109.86,113.67 84.45,113.67 82.55,111.76 82.55,109.22 23+2.P$2
N$59
  Top 0.61: +.P$1 86.04,93.03 83.82,90.81 77.47,90.81 74.93,88.27 74.93,85.41 26+2.P$2
N$60
  Top 0.61: 24+2.P$1 101.92,107 100.97,105.41 87,105.41 83.19,99.69 83.19,96.46 +.P$2
N$61
  Top 0.61: 23+2.P$1 24+2.P$2
N$62
  Top 0.61: 7+2.P$1 2+2.P$2
N$63
  Top 0.61: 27+2.P$1 7+2.P$2
N$64
  Top 0.61: 8+2.P$1 110.81,126.68 109.86,124.46 77.47,124.46 74.93,121.92 74.93,119.7 9+2.P$2
N$65
  Top 0.61: 20+2.P$1 69.3,100.78 67.31,105.41 52.07,105.41 50.8,106.68 50.16,107.63 19+2.P$2
N$66
  Top 0.61: 30+3.P$2 41.91,69.22 41.91,60.96 45.09,57.78 45.09,52.39 19+3.P$1
N$67
  Top 0.61: 30+3.P$1 44.77,76.52 41.91,78.74 32.38,78.74 32.38,76.52 29+3.P$2
N$68
  Top 0.61: 28+3.P$2 33.02,59.69 33.02,67.31 35.56,68.58 35.56,74.3 29+3.P$1
N$69
  Top 0.61: 27+3.P$2 33.02,43.18 33.02,54.61 35.56,57.15 35.56,59.69 28+3.P$1
N$70
  Top 0.61: 2+3.P$1 24.45,58.1 21.59,55.24 21.59,54.61 16.51,49.53 16.51,41.91 15.24,40.64 11.43,40.64 10.16,41.91 10.16,42.86 4+3.P$2
N$71
  Top 0.61: 4+3.P$1 13.02,44.77 12.7,45.09 8.89,46.67 8.89,58.42 9.53,59.37 6+3.P$2
N$72
  Top 0.61: 6+3.P$1 12.7,59.69 12.7,62.23 8.89,62.87 8.89,74.93 9.53,75.56 9.53,76.2 0+3.P$2
N$73
  Top 0.61: 0+3.P$1 13.09,78.5 8.89,79.29 8.89,90.81 5+3.P$2
N$74
  Top 0.61: 5+3.P$1 13.02,94.93 8.89,95.89 8.89,107.31 10.16,108.58 10.16,108.9 3+3.P$2
N$75
  Top 0.61: 3+3.P$1 1+3.P$2
N$76
  Top 0.61: 8+3.P$2 21.59,92.71 21.59,104.14 24.13,106.68 24.13,109.22 1+3.P$1
N$77
  Top 0.61: 9+3.P$1 24.77,76.2 24.77,79.38 28.57,83.82 28.57,104.78 33.02,107.95 33.02,109.22 21+3.P$2
N$78
  Top 0.61: 22+3.P$2 33.02,92.71 33.02,104.14 35.56,106.68 35.56,109.22 21+3.P$1
N$79
  Top 0.61: 23+3.P$2 41.27,84.45 36.2,89.53 36.2,92.71 22+3.P$1
N$80
  Top 0.61: 26+3.P$2 64.14,76.2 57.78,82.55 57.78,84.45 25+3.P$1
N$81
  Top 0.61: 24+3.P$1 44.77,99.38 46.35,97.79 46.35,97.16 54.61,88.9 54.61,85.15 25+3.P$2
N$82
  Top 0.61: 23+3.P$1 44.77,92.47 41.63,95.61 41.63,100.29 24+3.P$2
N$83
  Top 0.61: 7+3.P$1 24.45,47.94 28.57,51.44 28.57,61.59 26.04,62.87 22.23,62.87 20.95,62.23 20.95,59.69 2+3.P$2
N$84
  Top 0.61: 7+3.P$2 21.59,43.18 21.59,41.27 22.23,40.64 34.29,40.64 36.2,41.27 36.2,43.18 27+3.P$1
N$85
  Top 0.61: 9+3.P$2 21.59,76.2 21.59,87.63 24.13,90.17 24.13,92.71 8+3.P$1
N$86
  Bottom 0.61: R2.1 50.16,97.16 arc129 76.2,42.55 U$1.P$8 P4ZD1.C 83.69,47.96 C5.2
N$87
  Bottom 0.61: OK1.1 78.11,60.96 R4.1
N$88
  Bottom 0.61: R1.1 77.81,55.06 U$1.P$5 76.2,60.96 70.48,60.96 70.48,62.87 PH1.2
N$89
  Bottom 0.61: R5.1 104.78,77.34 104.78,85.09 102.36,87.5 R6.2
N$90
  Bottom 0.61: R9.2 R7.1
N$91
  Bottom 0.61: B2.+ 94.01,86.39 R16.P$1
N$92
  Bottom 0.61: R3.1 51.79,80.44 D2.A
N$93
  Bottom 0.61: OK1.3 75.56,67.31 81.28,67.31 81.22,56.77 96.97,56.84 97.03,77.54 92.71,79.38 Q2.2 90.38,79.73 Q1.2 89.85,81.39 P4ZD2.A 88.69,89.97 88.9,90.17 91.28,90.17 B2.-
N$94
  Bottom 0.61: OK1.4 79.69,71.75 81.28,71.75 81.28,78.74 83.19,78.74 82.7,79.22 R13.2 83.34,82.55 P4ZD2.C 85.3,81.71 85.72,81.28 85.72,80.62 Q2.1 87.42,79.73 Q1.1
N$95
  Bottom 0.61: U$1.P$3 63.5,53.34 63.5,57.78 73.03,57.78 R4.2
N$97
  Top 0.61: 19+3.P$2 41.59,49.85 41.7,49.6 46.6,49.53 46.53,51.44 50.16,69.77 57.78,69.85 57.78,67.37 +3.1.P$1
RECDR+
  Bottom 0.61: B1.+ 61.69,90.81 R10.P$1
VDD
  Bottom 0.61: D2.C 49.96,75.34 P4ZD3.C 51.3,70.42 C3.+ 57.15,62.09 C1.2 58.92,58.42 62.23,58.42 | 62.23,58.42 63.5,59.69 64.77,59.69 65.25,60.16 PH1.1 | U$1.P$2 62.87,50.8 62.23,51.44 62.23,58.42
VSS
  Bottom 0.61: C5.1 87,46.23 87,47.62 86.79,47.83 P4ZD1.A 87,50.59 87,50.8 84.45,50.8 | B1.- 61.56,93.38 59.69,95.25 52.07,95.25 50.16,92.08 C9.- 47.2,77.41 P4ZD3.A 47.13,70.55 C3.- 49.67,60.82 54.61,54.61 57.02,54.61 C1.1 57.15,50.8 arc41 73.03,44.45 73.03,50.8 U$1.P$7 78.89,50.8 R1.2 84.45,50.8 | 84.45,50.8 82.55,55.56 80.01,55.56 80.01,65.41 76.2,65.41 OK1.2

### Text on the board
Top: MICHAELS | 23112011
